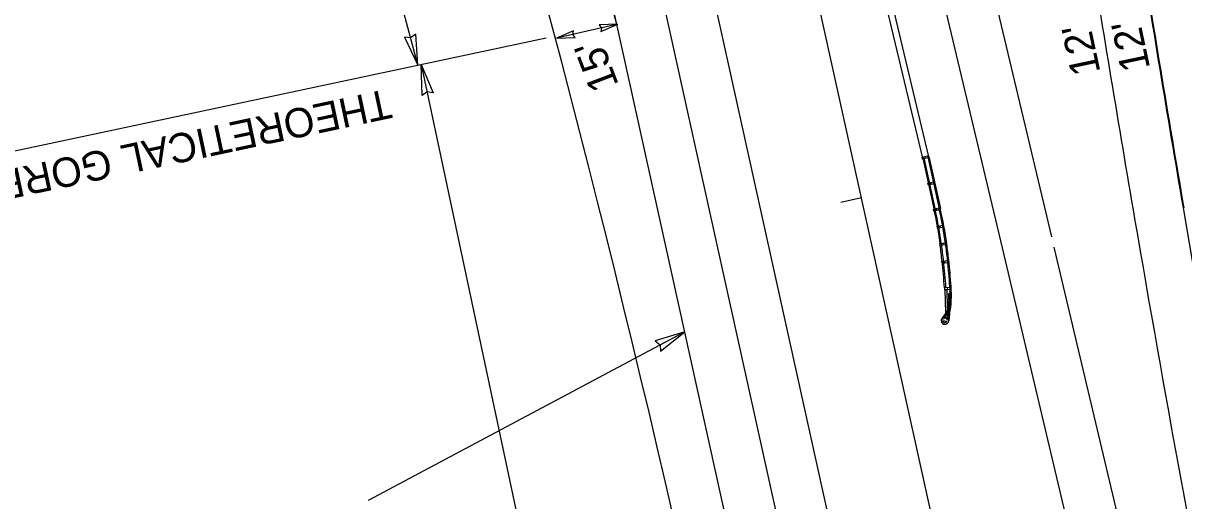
# Model space of a CAD drawing. Extents: x 578088 to 579220, y 1508751 to 1510400.
# Drawn here: x 578418.2 to 578695, y 1509092.1 to 1509206 of the extents above; entities that cross this region are included whole.
import ezdxf

# ---------------------------------------------------------------- set-up
doc = ezdxf.new("R2010")
doc.units = 0
for name, color, linetype in [('1', 7, 'Continuous'), ('18', 7, 'Continuous'), ('2', 7, 'Continuous'), ('28', 7, 'Continuous'), ('41', 7, 'Continuous'), ('46', 7, 'Continuous'), ('52', 7, 'Continuous')]:
    doc.layers.add(name, color=color, linetype=linetype)

msp = doc.modelspace()

# ---------------------------------------------------------------- linework, layer by layer
at = {"layer": '1'}
for p, q in [((578639.69, 1509066.69), (578362.17, 1510321.74)), ((578559.88, 1509205.29), (578315.3, 1510311.37))]:
    msp.add_line(p, q, dxfattribs=at)
at = {"layer": '18'}
for p, q in [((578659.48, 1508810.53), (578375.62, 1510094.27)), ((578663.47, 1509155.01), (578558.43, 1509596.29)), ((578688.9, 1509048.17), (578664.05, 1509152.58))]:
    msp.add_line(p, q, dxfattribs=at)
for radius, start, end in [(5741.58, 189.05897, 189.735667), (5729.75, 189.05897, 189.730018), (5729.75, 189.730019, 192.46846), (5741.58, 189.73613, 192.235242)]:
    msp.add_arc((584342.13, 1510130.3), radius, start, end, dxfattribs=at)
at = {"layer": '2'}
for p, q in [((578651.7, 1509152.41), (578547.48, 1509590.23)), ((578677.17, 1509045.38), (578651.7, 1509152.41))]:
    msp.add_line(p, q, dxfattribs=at)
at = {"layer": '28'}
msp.add_line((578618.1, 1509164.33), (578613.22, 1509163.25), dxfattribs=at)
at = {"layer": '41'}
for p, q in [((578671.2, 1508813.02), (578338.64, 1510317)), ((578614.13, 1508959.96), (578559.88, 1509205.29))]:
    msp.add_line(p, q, dxfattribs=at)
for centre, radius, start, end in [((574851.28, 1508229.92), 3819.72, 12.46859, 20.71859), ((574851.28, 1508229.92), 3834.72, 14.7352, 19.27173), ((584342.13, 1510130.3), 5729.58, 189.05897, 189.729939), ((584342.13, 1510130.3), 5729.58, 189.05897, 189.729939), ((584342.13, 1510130.3), 5729.58, 189.05897, 189.729939)]:
    msp.add_arc(centre, radius, start, end, dxfattribs=at)
at = {"layer": '46'}
for p, q in [((578632.73, 1509173.81), (578580.62, 1509392.73)), ((578634.19, 1509174.14), (578582.08, 1509393.05)), ((578632.56, 1509174.04), (578633.21, 1509174.19)), ((578632.68, 1509173.55), (578632.56, 1509174.04)), ((578633.33, 1509173.7), (578632.68, 1509173.55)), ((578632.73, 1509173.81), (578635.46, 1509161.41)), ((578632.97, 1509173.88), (578635.7, 1509161.47)), ((578633.21, 1509174.19), (578633.86, 1509174.34)), ((578633.21, 1509174.19), (578633.33, 1509173.7)), ((578633.97, 1509173.86), (578633.33, 1509173.7)), ((578633.86, 1509174.34), (578633.97, 1509173.86)), ((578633.92, 1509174.1), (578636.65, 1509161.7)), ((578634.19, 1509174.16), (578636.92, 1509161.76)), ((578633.95, 1509167.86), (578634.6, 1509168.01)), ((578634.6, 1509168.01), (578635.25, 1509168.15)), ((578634.6, 1509168.01), (578634.71, 1509167.52)), ((578635.25, 1509168.15), (578635.36, 1509167.66)), ((578634.06, 1509167.38), (578633.95, 1509167.86)), ((578634.71, 1509167.52), (578634.06, 1509167.38)), ((578635.36, 1509167.66), (578634.71, 1509167.52)), ((578635.29, 1509161.65), (578635.94, 1509161.79)), ((578635.4, 1509161.16), (578635.29, 1509161.65)), ((578636.05, 1509161.31), (578635.4, 1509161.16)), ((578635.94, 1509161.79), (578636.59, 1509161.94)), ((578635.94, 1509161.79), (578636.05, 1509161.31)), ((578636.7, 1509161.45), (578636.05, 1509161.31)), ((578636.59, 1509161.94), (578636.7, 1509161.45)), ((578636.16, 1509157.56), (578636.81, 1509157.68)), ((578636.25, 1509157.07), (578636.16, 1509157.56)), ((578636.9, 1509157.19), (578636.25, 1509157.07)), ((578636.81, 1509157.68), (578637.47, 1509157.8)), ((578636.81, 1509157.68), (578636.9, 1509157.19)), ((578637.56, 1509157.3), (578636.9, 1509157.19)), ((578637.47, 1509157.8), (578637.56, 1509157.3)), ((578636.82, 1509153.43), (578637.48, 1509153.52)), ((578636.88, 1509152.94), (578636.82, 1509153.43)), ((578637.54, 1509153.02), (578636.88, 1509152.94)), ((578637.48, 1509153.52), (578638.14, 1509153.6)), ((578637.48, 1509153.52), (578637.54, 1509153.02)), ((578638.2, 1509153.11), (578637.54, 1509153.02)), ((578638.14, 1509153.6), (578638.2, 1509153.11)), ((578637.3, 1509149.23), (578637.96, 1509149.3)), ((578637.3, 1509149.23), (578637.41, 1509149.24)), ((578637.3, 1509149.22), (578637.3, 1509149.23)), ((578637.35, 1509148.74), (578637.3, 1509149.23)), ((578638.01, 1509148.8), (578637.35, 1509148.74)), ((578637.96, 1509149.3), (578638.62, 1509149.37)), ((578637.96, 1509149.3), (578638.01, 1509148.8)), ((578638.67, 1509148.87), (578638.01, 1509148.8)), ((578638.62, 1509149.37), (578638.67, 1509148.87)), ((578637.91, 1509142.84), (578637.95, 1509142.42)), ((578637.91, 1509142.84), (578637.93, 1509142.84)), ((578639.21, 1509142.96), (578637.93, 1509142.86)), ((578637.93, 1509142.86), (578637.97, 1509142.42)), ((578639.25, 1509142.49), (578637.99, 1509142.39)), ((578637.99, 1509142.38), (578638.62, 1509142.43)), ((578638.22, 1509136.93), (578638.05, 1509142.38)), ((578638.66, 1509138.08), (578638.55, 1509142.43)), ((578638.56, 1509142.91), (578638.6, 1509142.44)), ((578638.56, 1509142.89), (578638.58, 1509142.9)), ((578638.62, 1509142.43), (578638.62, 1509142.44)), ((578638.87, 1509141.42), (578638.88, 1509140.06)), ((578639.42, 1509141.42), (578638.87, 1509141.42)), ((578638.9, 1509141.41), (578638.9, 1509141.45)), ((578638.9, 1509141.45), (578639.15, 1509141.45)), ((578638.93, 1509141.45), (578638.93, 1509141.45)), ((578638.93, 1509141.45), (578639.13, 1509141.45)), ((578638.94, 1509141.53), (578638.94, 1509141.45)), ((578638.97, 1509141.54), (578639.08, 1509141.54)), ((578638.98, 1509141.56), (578638.99, 1509141.57)), ((578638.98, 1509141.56), (578638.98, 1509141.54)), ((578638.99, 1509141.57), (578639.06, 1509141.57)), ((578638.99, 1509141.53), (578638.99, 1509141.45)), ((578639.06, 1509141.57), (578639.07, 1509141.56)), ((578639.06, 1509141.53), (578639.06, 1509141.45)), ((578639.07, 1509141.56), (578639.07, 1509141.54)), ((578639.11, 1509141.53), (578639.11, 1509141.45)), ((578639.13, 1509141.45), (578639.13, 1509141.45)), ((578639.15, 1509141.45), (578639.15, 1509141.42)), ((578639.42, 1509141.41), (578639.43, 1509140.06)), ((578637.91, 1509135.99), (578639.02, 1509137.74)), ((578638.98, 1509140.06), (578638.53, 1509137.28)), ((578639.05, 1509140.06), (578638.61, 1509137.37)), ((578638.66, 1509137.42), (578638.65, 1509137.62)), ((578638.7, 1509137.45), (578638.68, 1509137.77)), ((578639.43, 1509140.07), (578638.88, 1509140.06)), ((578638.93, 1509137.86), (578638.94, 1509137.87)), ((578638.93, 1509137.86), (578638.93, 1509137.84)), ((578638.93, 1509137.84), (578638.94, 1509137.83)), ((578638.97, 1509137.87), (578638.94, 1509137.87)), ((578638.94, 1509137.83), (578638.96, 1509137.83)), ((578638.97, 1509137.88), (578638.96, 1509137.81)), ((578638.97, 1509137.82), (578639.02, 1509137.82)), ((578638.97, 1509137.79), (578639.01, 1509137.79)), ((578639.03, 1509137.89), (578638.98, 1509137.9)), ((578638.98, 1509137.87), (578639.02, 1509137.86)), ((578639.03, 1509137.94), (578639.01, 1509137.75)), ((578639.03, 1509137.94), (578639.04, 1509137.94)), ((578637.16, 1509134.96), (578637.2, 1509134.86)), ((578637.19, 1509134.82), (578637.19, 1509134.82)), ((578637.19, 1509134.82), (578637.19, 1509134.82)), ((578637.3, 1509134.89), (578637.29, 1509134.87)), ((578638.23, 1509136.93), (578637.33, 1509135.63)), ((578637.89, 1509135.95), (578637.33, 1509135.63)), ((578638.23, 1509136.93), (578637.34, 1509135.62)), ((578637.35, 1509135.64), (578637.89, 1509135.95)), ((578637.36, 1509134.85), (578637.35, 1509134.83)), ((578637.55, 1509135.26), (578637.54, 1509135.24)), ((578637.61, 1509135.21), (578637.6, 1509135.2)), ((578637.8, 1509135.62), (578637.79, 1509135.6)), ((578637.8, 1509136.14), (578637.94, 1509136.36)), ((578637.86, 1509135.58), (578637.85, 1509135.56)), ((578638, 1509136.31), (578637.86, 1509136.1)), ((578638.19, 1509136.43), (578637.99, 1509136.57)), ((578638.45, 1509135.5), (578638, 1509135.67)), ((578638.1, 1509135.98), (578638.17, 1509136.39)), ((578638.13, 1509135.97), (578638.1, 1509135.98)), ((578638.11, 1509135.89), (578638.19, 1509136.42)), ((578638.74, 1509135.79), (578638.11, 1509135.89)), ((578638.75, 1509135.86), (578638.12, 1509135.96)), ((578638.19, 1509136.44), (578638.34, 1509136.41)), ((578638.19, 1509136.42), (578638.82, 1509136.33)), ((578638.21, 1509136.73), (578638.22, 1509136.74)), ((578638.42, 1509136.8), (578638.23, 1509136.93)), ((578638.25, 1509136.43), (578638.24, 1509136.52)), ((578638.25, 1509135.79), (578638.26, 1509135.86)), ((578638.29, 1509136.7), (578638.27, 1509136.68)), ((578638.27, 1509135.78), (578638.4, 1509135.76)), ((578638.29, 1509135.79), (578638.3, 1509135.86)), ((578638.29, 1509135.78), (578638.29, 1509135.74)), ((578638.29, 1509135.74), (578638.29, 1509135.73)), ((578638.29, 1509135.73), (578638.36, 1509135.72)), ((578638.35, 1509136.47), (578638.34, 1509136.4)), ((578638.37, 1509135.72), (578638.36, 1509135.72)), ((578638.37, 1509136.48), (578638.5, 1509136.46)), ((578638.38, 1509135.76), (578638.37, 1509135.72)), ((578638.39, 1509136.46), (578638.38, 1509136.39)), ((578638.38, 1509135.78), (578638.39, 1509135.84)), ((578638.4, 1509136.47), (578638.43, 1509136.71)), ((578638.42, 1509135.77), (578638.43, 1509135.84)), ((578638.42, 1509134.9), (578638.42, 1509134.88)), ((578638.43, 1509136.71), (578638.52, 1509136.69)), ((578638.46, 1509136.87), (578638.44, 1509136.71)), ((578638.48, 1509136.45), (578638.47, 1509136.38)), ((578638.48, 1509136.46), (578638.52, 1509136.69)), ((578638.49, 1509135.33), (578638.48, 1509135.31)), ((578638.5, 1509134.88), (578638.49, 1509134.86)), ((578638.56, 1509137.01), (578638.51, 1509136.69)), ((578638.52, 1509136.44), (578638.51, 1509136.37)), ((578638.51, 1509136.39), (578638.82, 1509136.34)), ((578638.56, 1509135.32), (578638.56, 1509135.3)), ((578638.66, 1509137.41), (578638.66, 1509137.43)), ((578638.76, 1509136.35), (578638.71, 1509137.25)), ((578638.86, 1509136.61), (578638.72, 1509135.64)), ((578638.72, 1509135.64), (578638.9, 1509135.03)), ((578638.82, 1509136.33), (578638.75, 1509135.86)), ((578638.89, 1509135.97), (578638.85, 1509135.71)), ((578638.86, 1509136.61), (578639.13, 1509136.57)), ((578639.13, 1509136.57), (578638.9, 1509135.01)), ((578639.14, 1509136.58), (578638.91, 1509135.01)), ((578639.14, 1509136.58), (578638.92, 1509136.88)), ((578638.92, 1509136.88), (578638.92, 1509136.87)), ((578639.13, 1509136.57), (578638.92, 1509136.87)), ((578638.92, 1509135.7), (578638.96, 1509135.96)), ((578638.94, 1509136.44), (578638.94, 1509136.42)), ((578639.01, 1509136.41), (578639.02, 1509136.43)), ((578637.27, 1509134.65), (578637.26, 1509134.65)), ((578637.34, 1509134.53), (578637.3, 1509134.64)), ((578637.5, 1509134.37), (578637.61, 1509134.34)), ((578637.62, 1509134.3), (578637.62, 1509134.31)), ((578637.79, 1509134.23), (578637.8, 1509134.24)), ((578637.93, 1509134.21), (578637.83, 1509134.25)), ((578638.16, 1509134.21), (578638.26, 1509134.26)), ((578638.16, 1509134.21), (578638.26, 1509134.26)), ((578638.29, 1509134.25), (578638.3, 1509134.24)), ((578638.3, 1509134.24), (578638.29, 1509134.25)), ((578638.36, 1509134.46), (578638.35, 1509134.44)), ((578638.43, 1509134.45), (578638.43, 1509134.43)), ((578638.47, 1509134.32), (578638.47, 1509134.32)), ((578638.58, 1509134.39), (578638.48, 1509134.36))]:
    msp.add_line(p, q, dxfattribs=at)
msp.add_circle((578637.92, 1509134.81), 0.25, dxfattribs=at)
for centre, radius, start, end in [((578637.99, 1509142.42), 0.0423, 184.766, 274.766), ((578637.99, 1509142.42), 0.0267, 184.766, 274.766), ((578638.29, 1509142.4), 0.0417, 184.766, 4.766), ((578638.97, 1509141.5), 0.0374, 49.0302, 131.4244), ((578639.03, 1509141.47), 0.0674, 59.8574, 120.5972), ((578639.08, 1509141.5), 0.0374, 49.0302, 131.4244), ((578639, 1509137.84), 0.0335, 128.4484, 219.1028), ((578638.98, 1509137.8), 0.0159, 105.7077, 241.8435), ((578638.98, 1509137.88), 0.0159, 105.7077, 241.8435), ((578638.03, 1509135.08), 0.887, 141.8882, 355.264), ((578638.03, 1509135.09), 0.887, 160.5258, 188.5762), ((578638.03, 1509135.08), 0.877, 141.8882, 355.264), ((578638.03, 1509135.09), 0.887, 197.5339, 209.6185), ((578637.18, 1509134.85), 0.0267, 293.5761, 27.0398), ((578637.32, 1509134.85), 0.0383, 145.5762, 325.5762), ((578637.33, 1509134.87), 0.0383, 325.5762, 145.5762), ((578637.57, 1509135.22), 0.0383, 145.5762, 325.5762), ((578637.58, 1509135.23), 0.0383, 325.5762, 145.5762), ((578637.82, 1509135.58), 0.0383, 145.5762, 325.5762), ((578637.82, 1509136.12), 0.0367, 145.5762, 325.5762), ((578637.83, 1509135.6), 0.0383, 325.5762, 145.5762), ((578638.08, 1509135.86), 0.21, 145.5762, 248.5762), ((578637.97, 1509136.33), 0.0367, 325.5762, 145.5762), ((578638.24, 1509136.7), 0.0383, 145.5759, 325.5759), ((578638.25, 1509136.72), 0.0383, 325.5759, 145.5759), ((578638.27, 1509135.8), 0.021, 189.319, 333.8333), ((578638.34, 1509135.84), 0.0719, 224.4419, 298.7105), ((578638.37, 1509136.45), 0.021, 9.319, 153.8333), ((578638.4, 1509135.78), 0.021, 189.319, 333.8333), ((578638.43, 1509136.39), 0.0719, 44.4419, 118.7105), ((578638.46, 1509134.89), 0.0383, 351.5762, 171.5762), ((578638.46, 1509134.87), 0.0383, 171.5762, 351.5762), ((578638.52, 1509135.69), 0.21, 248.5762, 341.677), ((578638.5, 1509136.44), 0.021, 9.319, 153.8333), ((578638.52, 1509135.31), 0.0383, 171.5762, 351.5762), ((578638.52, 1509135.33), 0.0383, 351.5762, 171.5762), ((578638.5, 1509136.39), 0.0417, 351.5761, 64.9368), ((578638.03, 1509135.09), 0.887, 308.5762, 336.6266), ((578638.88, 1509135.7), 0.0367, 171.5762, 351.5762), ((578638.92, 1509135.96), 0.0367, 351.5762, 171.5762), ((578638.98, 1509136.44), 0.0383, 351.5764, 171.5764), ((578638.97, 1509136.42), 0.0383, 171.5764, 351.5764), ((578637.27, 1509134.63), 0.0267, 20.1128, 113.5762), ((578638.03, 1509135.09), 0.887, 218.5762, 233.5762), ((578637.6, 1509134.31), 0.0267, 338.5762, 72.0399), ((578638.03, 1509135.09), 0.887, 242.5338, 254.6185), ((578637.82, 1509134.23), 0.0267, 65.1124, 158.5762), ((578638.03, 1509135.09), 0.887, 263.5762, 278.5762), ((578638.27, 1509134.23), 0.0267, 23.5762, 117.0396), ((578638.27, 1509134.23), 0.0267, 23.5762, 117.0399), ((578638.03, 1509135.09), 0.887, 287.5339, 299.6185), ((578638.39, 1509134.43), 0.0383, 171.5762, 351.5762), ((578638.39, 1509134.45), 0.0383, 351.5762, 171.5762), ((578638.49, 1509134.33), 0.0267, 110.1128, 203.5762)]:
    msp.add_arc(centre, radius, start, end, dxfattribs=at)
for centre, major_axis, ratio, start_param, end_param in [((578550.81, 1509141.99), (20.86, -87.61), 0.964286, 1.468642, 1.562826), ((578550.78, 1509141.99), (20.93, -87.88), 0.964395, 1.468642, 1.562826), ((578552, 1509142.28), (20.86, -87.61), 0.964286, 1.468642, 1.562826), ((578552, 1509142.28), (20.93, -87.88), 0.964395, 1.468642, 1.562826), ((578510.2, 1509136.87), (31.16, -130.86), 0.948697, 1.440864, 1.468634), ((578513.48, 1509137.5), (30.61, -128.57), 0.943102, 1.439674, 1.468634), ((578511.49, 1509137.29), (31.16, -130.86), 0.948697, 1.439884, 1.468634), ((578514.7, 1509137.78), (30.61, -128.57), 0.943102, 1.439551, 1.468634), ((578510.2, 1509136.87), (31.16, -130.86), 0.948697, 1.393285, 1.440864), ((578513.48, 1509137.5), (30.61, -128.57), 0.943102, 1.39137, 1.439674), ((578511.49, 1509137.29), (31.16, -130.86), 0.948697, 1.393285, 1.439884), ((578514.7, 1509137.78), (30.61, -128.57), 0.943102, 1.39137, 1.439551), ((578610.86, 1509140.41), (27.73, 6.6), 0.937456, 5.89231, 6.141691), ((578611.14, 1509140.37), (27.73, 6.6), 0.937456, 5.89231, 6.141691), ((578642.22, 1509132.05), (0.8, 7.04), 0.813532, 0.727223, 0.900583), ((578642.22, 1509132.05), (0.8, 7.03), 0.813845, 0.726535, 0.900584)]:
    msp.add_ellipse(centre, major_axis=major_axis, ratio=ratio, start_param=start_param, end_param=end_param, dxfattribs=at)
at = {"layer": '52'}
for p, q in [((578560.04, 1509205.69), (578545.41, 1509202.41)), ((578549.47, 1509204.15), (578545.41, 1509202.41)), ((578549.33, 1509203.29), (578549.47, 1509204.15)), ((578560.04, 1509205.69), (578555.61, 1509205.56)), ((578555.61, 1509205.56), (578556.12, 1509204.81)), ((578555.97, 1509203.95), (578560.04, 1509205.69)), ((578556.12, 1509204.81), (578555.97, 1509203.95)), ((578405.02, 1509173.15), (578542.9, 1509202.46)), ((578510.62, 1509202.44), (578509.18, 1509202.63)), ((578509.18, 1509202.63), (578512.32, 1509195.96)), ((578511.84, 1509203.32), (578510.62, 1509202.44)), ((578512.32, 1509195.96), (578511.84, 1509203.32)), ((578545.41, 1509202.41), (578549.83, 1509202.54)), ((578549.83, 1509202.54), (578549.33, 1509203.29)), ((578513.15, 1509196.13), (578592.43, 1508823.18)), ((578513.15, 1509196.13), (578516.03, 1509189.33)), ((578513.34, 1509188.76), (578513.15, 1509196.13)), ((578514.55, 1509189.58), (578513.34, 1509188.76)), ((578516.03, 1509189.33), (578514.55, 1509189.58)), ((578575.99, 1509132.43), (578500.53, 1509092.24)), ((578575.99, 1509132.43), (578568.94, 1509130.26)), ((578570.23, 1509127.83), (578575.99, 1509132.43)), ((578568.94, 1509130.26), (578570.08, 1509129.28)), ((578570.08, 1509129.28), (578570.23, 1509127.83))]:
    msp.add_line(p, q, dxfattribs=at)
msp.add_arc((574817.44, 1508227.41), 3819.72, 14.68854, 19.14283, dxfattribs=at)

# ---------------------------------------------------------------- texts
for s, rotation, p in [("12'", 102, (578675.12, 1509194.29)), ("12'", 102, (578686.97, 1509195.24)), ("15'", 110.8713, (578560.32, 1509191.24)), ('THEORETICAL GORE', 192, (578505.14, 1509190.33))]:
    msp.add_text(s, height=7, rotation=rotation, dxfattribs=at).set_placement(p)

doc.saveas('drawing.dxf')
